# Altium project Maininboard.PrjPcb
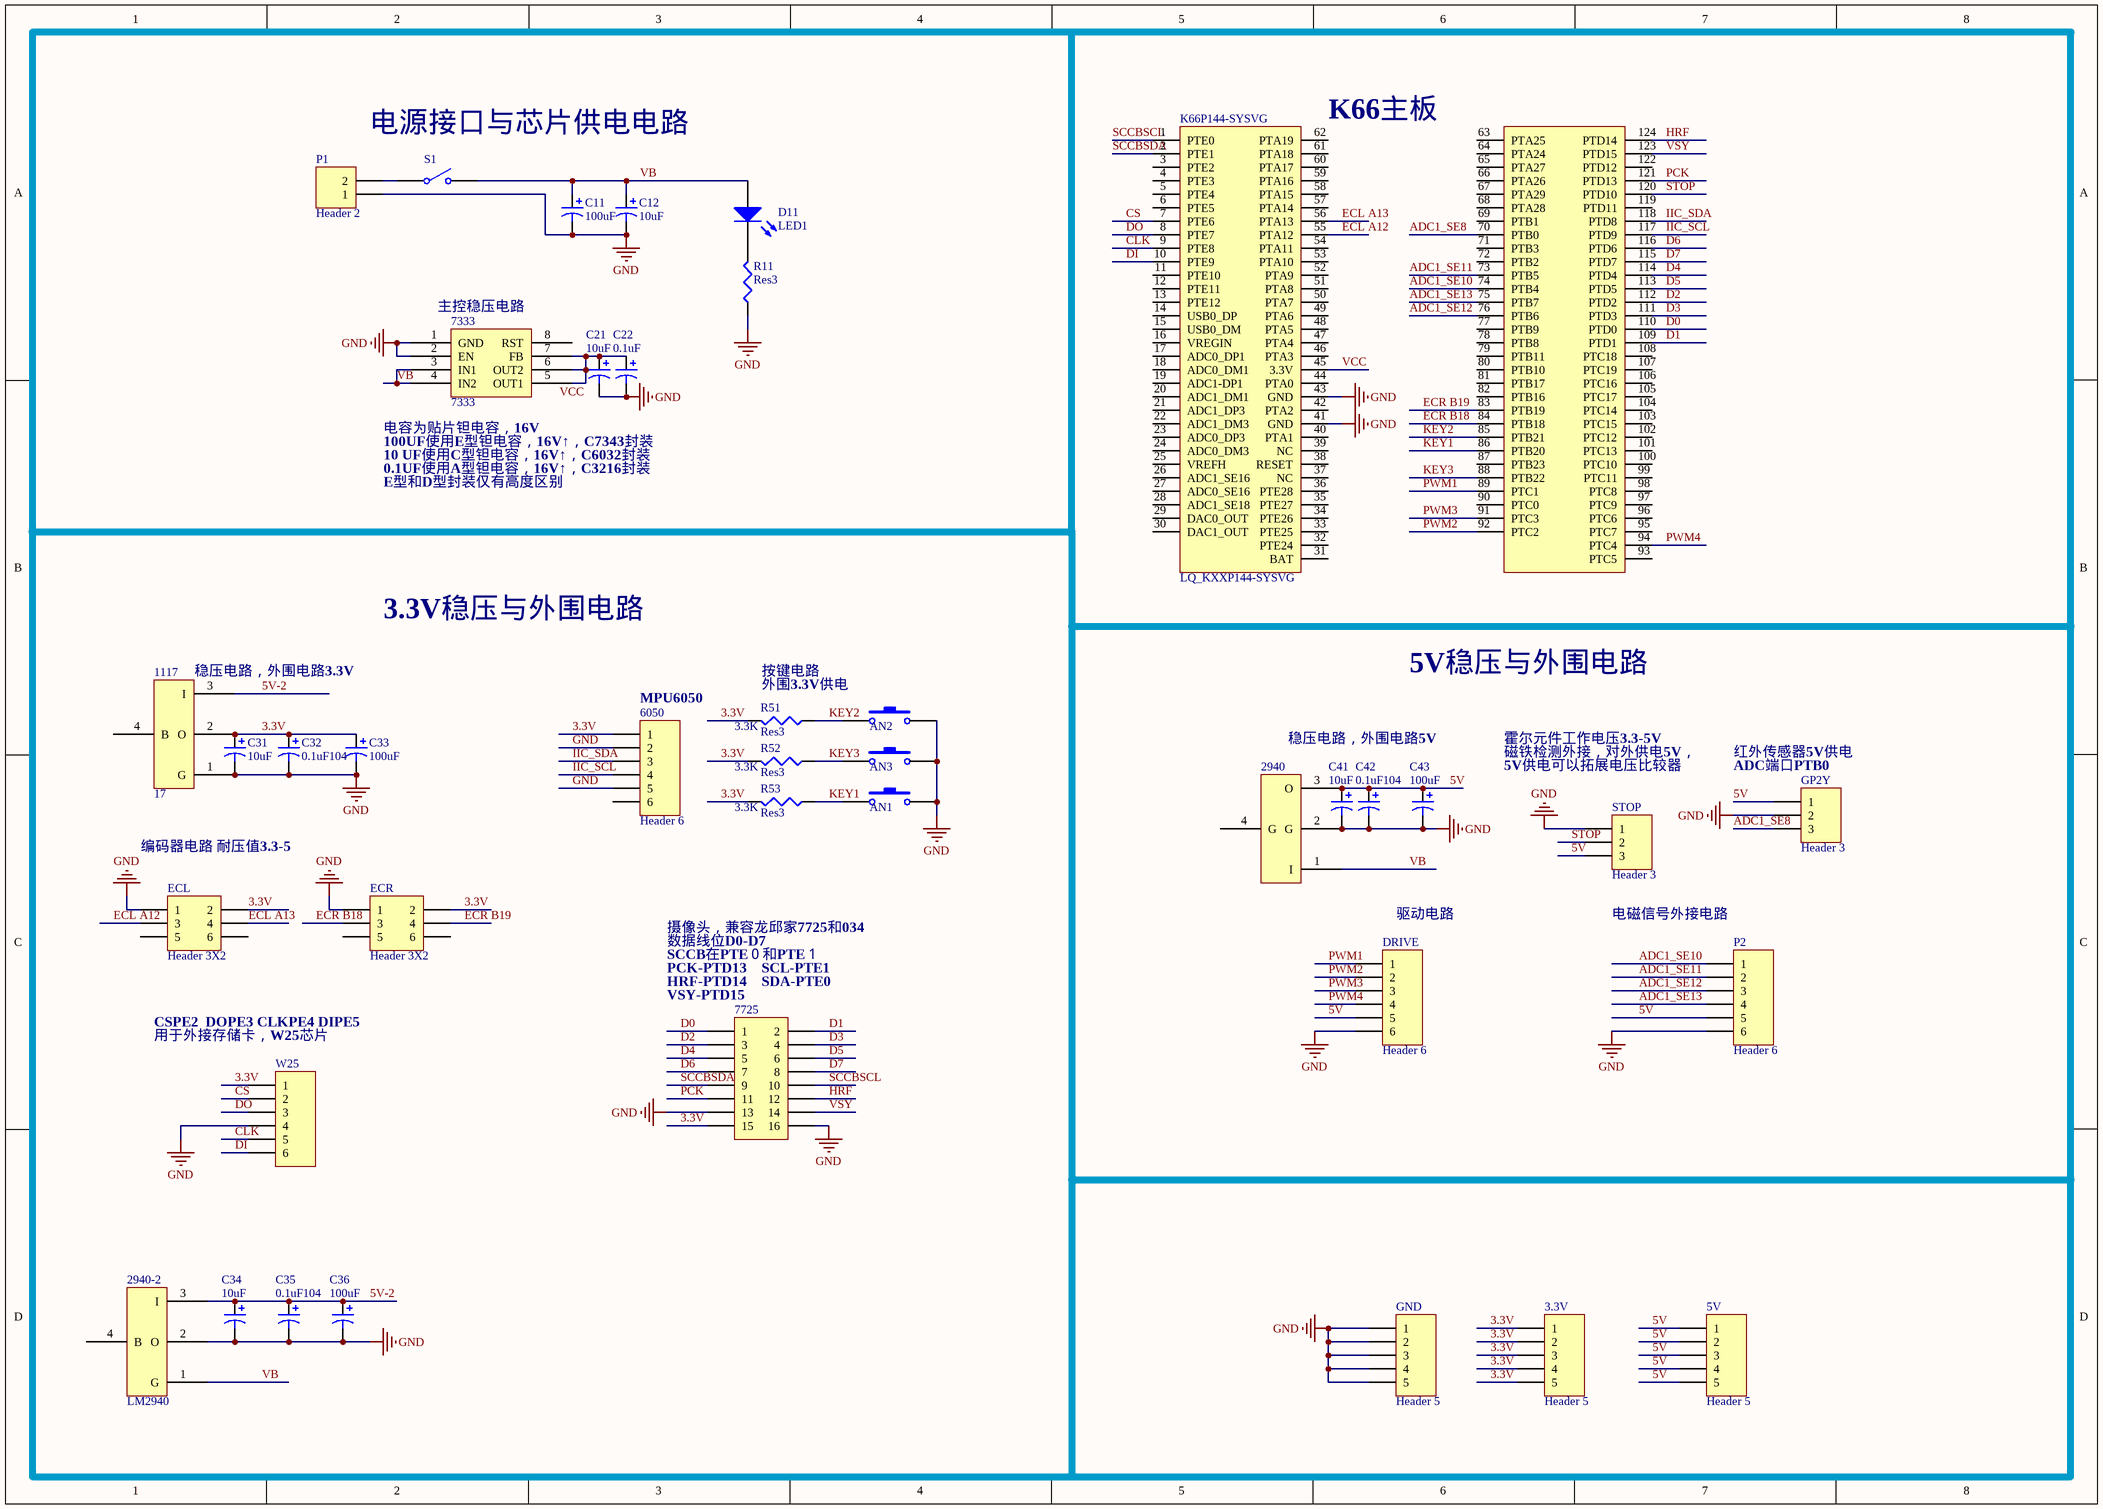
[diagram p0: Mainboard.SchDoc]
1 sheet, 40 parts. Net scope: global (net labels, ports and power ports of the same name join across sheets).
Board file: Mainboard.PcbDoc

## Sheet Mainboard.SchDoc
size A3

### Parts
3.3V  Header 5  [HDR1X5]
5V  Header 5  [HDR1X5]
1117  17  [SOT-223]
2940  40-1  [TO-220B]  (value not drawn)
2940-2  LM2940  [TO-220B]
6050  Header 6  [HX2.54-6]
7333  7333  [SO8_N]
7725  Header 8X2  [HDR2X8]  (value not drawn)
AN1  Button  [SMT4*6*2.5]  (value not drawn)
AN2  Button  [SMT4*6*2.5]  (value not drawn)
AN3  Button  [SMT4*6*2.5]  (value not drawn)
C11  value 100uF  [C7343]  (hidden comment: Cap Pol3)
C12  value 10uF  [C6032]  (hidden comment: Cap Pol3)
C21  value 10uF  [C6032]  (hidden comment: Cap Pol3)
C22  value 0.1uF  [C3216]  (hidden comment: Cap Pol3)
C31  value 10uF  [C6032]  (hidden comment: Cap Pol3)
C32  value 0.1uF104  [C3216]  (hidden comment: Cap Pol3)
C33  value 100uF  [C7343]  (hidden comment: Cap Pol3)
C34  value 10uF  [C6032]  (hidden comment: Cap Pol3)
C35  value 0.1uF104  [C3216]  (hidden comment: Cap Pol3)
C36  value 100uF  [C7343]  (hidden comment: Cap Pol3)
C41  value 10uF  [C6032]  (hidden comment: Cap Pol3)
C42  value 0.1uF104  [C3216]  (hidden comment: Cap Pol3)
C43  value 100uF  [C7343]  (hidden comment: Cap Pol3)
D11  LED1  [C1206]
DRIVE  Header 6  [HX2.54-6]
ECL  Header 3X2  [HDR2X3]
ECR  Header 3X2  [HDR2X3]
GND  Header 5  [HDR1X5]
GP2Y  Header 3  [HX2.54-3]
K66P144-SYSVG  LQ_KXXP144-SYSVG  [LQ_KXXP144-SYSVG]
P1  Header 2  [2PIN-5.08A]
P2  Header 6  [HDR1X6]
R11  Res3  [R0805]
R51  Res3  value 3.3K  [R0805]
R52  Res3  value 3.3K  [R0805]
R53  Res3  value 3.3K  [R0805]
S1  S2W  [SW-TO3]  (value not drawn)
STOP  Header 3  [HX2.54-3]
W25  MHDR1X6  [HDR1X6]  (value not drawn)

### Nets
GND: 1117.1(G) 2940.2(G) 2940-2.2(O) 6050.2 6050.5 7333.1(GND) 7333.2(EN) 7725.13 7725.16 AN1.1 AN2.1 AN3.1 C11.2 C12.2 C21.2 C22.2 C31.2 C32.2 C33.2 C34.2 C35.2 C36.2 C41.2 C42.2 C43.2 DRIVE.6 ECL.1 ECR.1 GND.1 GND.2 GND.3 GND.4 GND.5 GP2Y.2 K66P144-SYSVG.41(GND) K66P144-SYSVG.43(GND) P1.1 P2.6 R11.1 STOP.1 W25.4
3.3V: 3.3V.1 3.3V.2 3.3V.3 3.3V.4 3.3V.5 1117.2(O) 6050.1 7725.15 C31.1 C32.1 C33.1 ECL.2 ECR.2 R51.2 R52.2 R53.2 W25.1
5V: 5V.1 5V.2 5V.3 5V.4 5V.5 2940.3(O) C41.1 C42.1 C43.1 DRIVE.5 GP2Y.1 P2.5 STOP.3
5V-2: 1117.3(I) 2940-2.3(I) C34.1 C35.1 C36.1
ADC1_SE8: GP2Y.3 K66P144-SYSVG.70(PTB0)
ADC1_SE10: K66P144-SYSVG.74(PTB4) P2.1
ADC1_SE11: K66P144-SYSVG.73(PTB5) P2.2
ADC1_SE12: K66P144-SYSVG.76(PTB6) P2.3
ADC1_SE13: K66P144-SYSVG.75(PTB7) P2.4
CLK: K66P144-SYSVG.9(PTE8) W25.5
CS: K66P144-SYSVG.7(PTE6) W25.2
D0: 7725.1 K66P144-SYSVG.110(PTD0)
D1: 7725.2 K66P144-SYSVG.109(PTD1)
D2: 7725.3 K66P144-SYSVG.112(PTD2)
D3: 7725.4 K66P144-SYSVG.111(PTD3)
D4: 7725.5 K66P144-SYSVG.114(PTD4)
D5: 7725.6 K66P144-SYSVG.113(PTD5)
D6: 7725.7 K66P144-SYSVG.116(PTD6)
D7: 7725.8 K66P144-SYSVG.115(PTD7)
DI: K66P144-SYSVG.10(PTE9) W25.6
DO: K66P144-SYSVG.8(PTE7) W25.3
ECL A12: ECL.3 K66P144-SYSVG.55(PTA12)
ECL A13: ECL.4 K66P144-SYSVG.56(PTA13)
ECR B18: ECR.3 K66P144-SYSVG.84(PTB18)
ECR B19: ECR.4 K66P144-SYSVG.83(PTB19)
HRF: 7725.12 K66P144-SYSVG.124(PTD14)
IIC_SCL: 6050.4 K66P144-SYSVG.117(PTD9)
IIC_SDA: 6050.3 K66P144-SYSVG.118(PTD8)
KEY1: AN1.2 K66P144-SYSVG.86(PTB20) R53.1
KEY2: AN2.2 K66P144-SYSVG.85(PTB21) R51.1
KEY3: AN3.2 K66P144-SYSVG.88(PTB22) R52.1
PCK: 7725.11 K66P144-SYSVG.121(PTD13)
PWM1: DRIVE.1 K66P144-SYSVG.89(PTC1)
PWM2: DRIVE.2 K66P144-SYSVG.92(PTC2)
PWM3: DRIVE.3 K66P144-SYSVG.91(PTC3)
PWM4: DRIVE.4 K66P144-SYSVG.94(PTC4)
SCCBSCL: 7725.10 K66P144-SYSVG.1(PTE0)
SCCBSDA: 7725.9 K66P144-SYSVG.2(PTE1)
STOP: K66P144-SYSVG.120(PTD10) STOP.2
VB: 2940.1(I) 2940-2.1(G) 7333.3(IN1) 7333.4(IN2) C11.1 C12.1 D11.1(A) S1.2(NO)
VCC: 7333.5(OUT1) 7333.6(OUT2) 7333.7(FB) C21.1 C22.1 K66P144-SYSVG.45(3.3V)
VSY: 7725.14 K66P144-SYSVG.123(PTD15)
NetD11_2: D11.2(K) R11.2
NetP1_2: P1.2 S1.1(COMMON)

Not connected (* = marked no-connect by the designer): 1117 4(B); 2940 4(G); 2940-2 4(B); 6050 6; 7333 8(RST); ECL 5 6; ECR 5 6; K66P144-SYSVG 3(PTE2) 4(PTE3) 5(PTE4) 6(PTE5) 11(PTE10) 12(PTE11) 13(PTE12) 14(USB0_DP) 15(USB0_DM) 16(VREGIN) 17(ADC0_DP1) 18(ADC0_DM1) 19(ADC1-DP1) 20(ADC1_DM1) 21(ADC1_DP3) 22(ADC1_DM3) 23(ADC0_DP3) 24(ADC0_DM3) 25(VREFH) 26(ADC1_SE16) 27(ADC0_SE16) 28(ADC1_SE18) 29(DAC0_OUT) 30(DAC1_OUT) 31(BAT) 32(PTE24) 33(PTE25) 34(PTE26) 35(PTE27) 36(PTE28) 37(NC) 38(RESET) 39(NC) 40(PTA1) 42(PTA2) 44(PTA0) 46(PTA3) 47(PTA4) 48(PTA5) 49(PTA6) 50(PTA7) 51(PTA8) 52(PTA9) 53(PTA10) 54(PTA11) 57(PTA14) 58(PTA15) 59(PTA16) 60(PTA17) 61(PTA18) 62(PTA19) 63(PTA25) 64(PTA24) 65(PTA27) 66(PTA26) 67(PTA29) 68(PTA28) 69(PTB1) 71(PTB3) 72(PTB2) 77(PTB9) 78(PTB8) 79(PTB11) 80(PTB10) 81(PTB17) 82(PTB16) 87(PTB23) 90(PTC0) 93(PTC5) 95(PTC7) 96(PTC6) 97(PTC9) 98(PTC8) 99(PTC11) 100(PTC10) 101(PTC13) 102(PTC12) 103(PTC15) 104(PTC14) 105(PTC17) 106(PTC16) 107(PTC19) 108(PTC18) 119(PTD11) 122(PTD12)

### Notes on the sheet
- 电源接口与芯片供电电路
- (near K66P144-SYSVG) K66主板
- (near 7333) 主控稳压电路
- (near 7333) 电容为贴片钽电容，16V
- 100UF使用E型钽电容，16V↑，C7343封装
- 10 UF使用C型钽电容，16V↑，C6032封装
- 0.1UF使用A型钽电容，16V↑，C3216封装
- E型和D型封装仅有高度区别
- 3.3V稳压与外围电路
- (near 1117) 稳压电路，外围电路3.3V
- (near 6050) MPU6050
- (near R51) 按键电路
- (near R51) 外围3.3V供电
- 5V稳压与外围电路
- 稳压电路，外围电路5V
- 霍尔元件工作电压3.3-5V
- 磁铁检测外接，对外供电5V，
- 5V供电可以拓展电压比较器
- (near GP2Y) 红外传感器5V供电
- (near GP2Y) ADC端口PTB0
- 编码器电路 耐压值3.3-5
- (near DRIVE) 驱动电路
- 电磁信号外接电路
- 摄像头，兼容龙邱家7725和034
- 数据线位D0-D7
- SCCB在PTE０和PTE１
- (near 7725) HRF-PTD14
- PCK-PTD13
- SCL-PTE1
- (near 7725) SDA-PTE0
- (near W25) 用于外接存储卡，W25芯片
- CSPE2  DOPE3 CLKPE4 DIPE5
- (near 7725) VSY-PTD15

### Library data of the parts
3.3V 5V GND = Header 5: Header, 5-Pin
1117 = AMS1117: SOT-223
2940 2940-2 = LM2940: SOT-223
6050 DRIVE P2 = Header 6: Header, 6-Pin
7725 = Header 8X2: Header, 8-Pin, Dual row
C11 C12 C21 C22 C31-C36 C41-C43 = Cap Pol3: Polarized Capacitor (Surface Mount)
D11 = LED3: Typical BLUE SiC LED
ECL ECR = Header 3X2: Header, 3-Pin, Dual row
GP2Y STOP = Header 3: Header, 3-Pin
P1 = Header 2: Header, 2-Pin
R11 R51-R53 = Res3: Resistor
S1 = SW-SPST: Single-Pole, Single-Throw Switch
W25 = MHDR1X6: Header, 6-Pin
